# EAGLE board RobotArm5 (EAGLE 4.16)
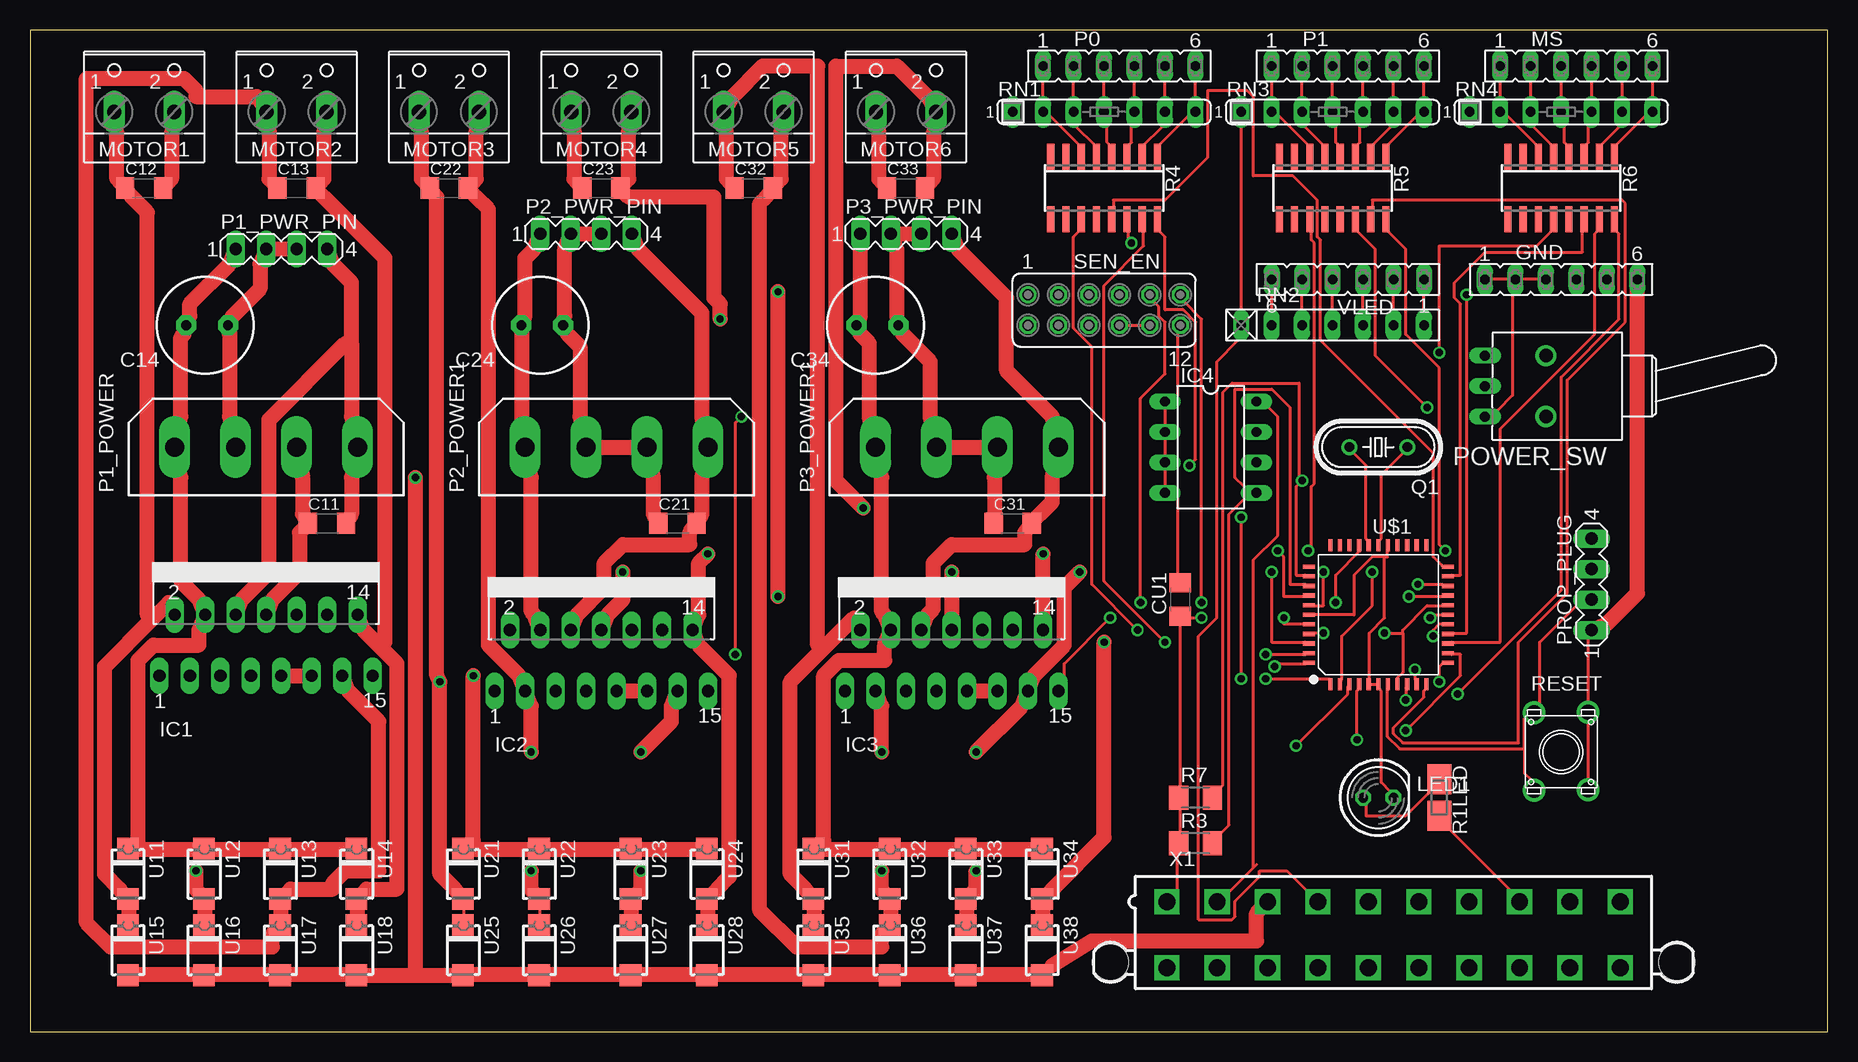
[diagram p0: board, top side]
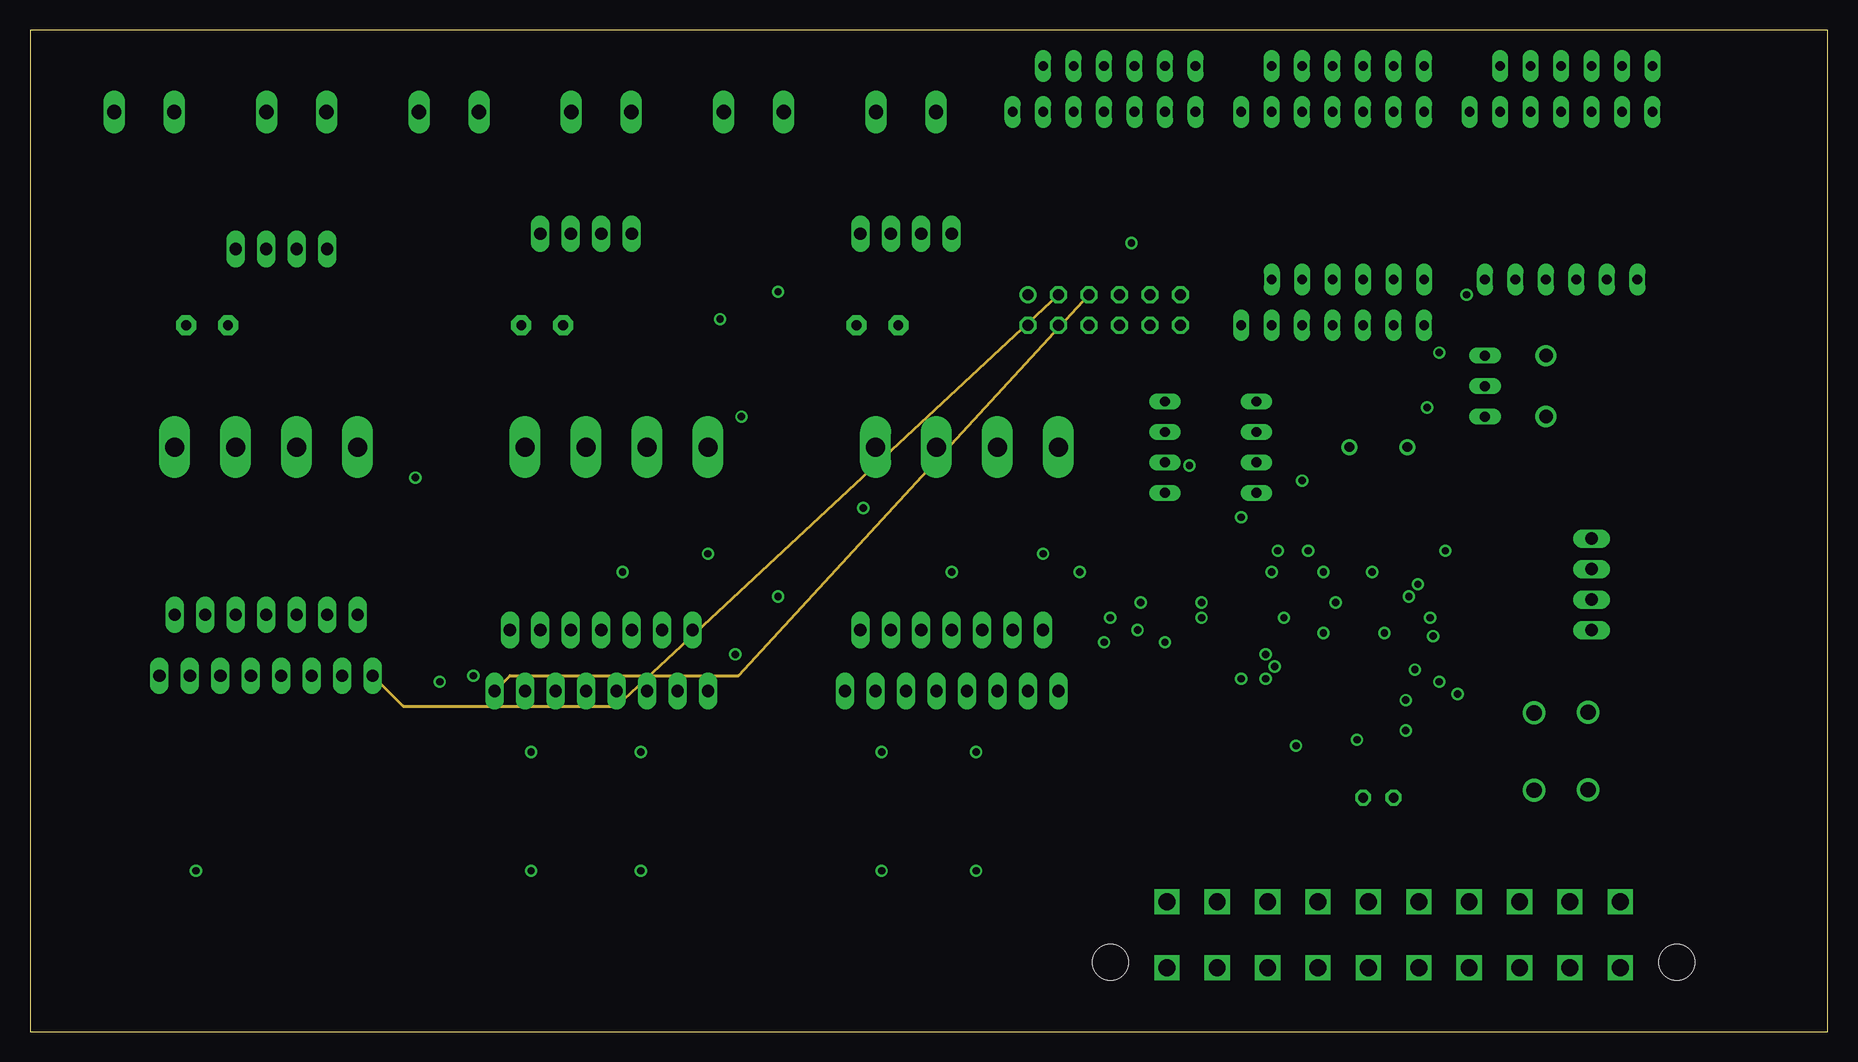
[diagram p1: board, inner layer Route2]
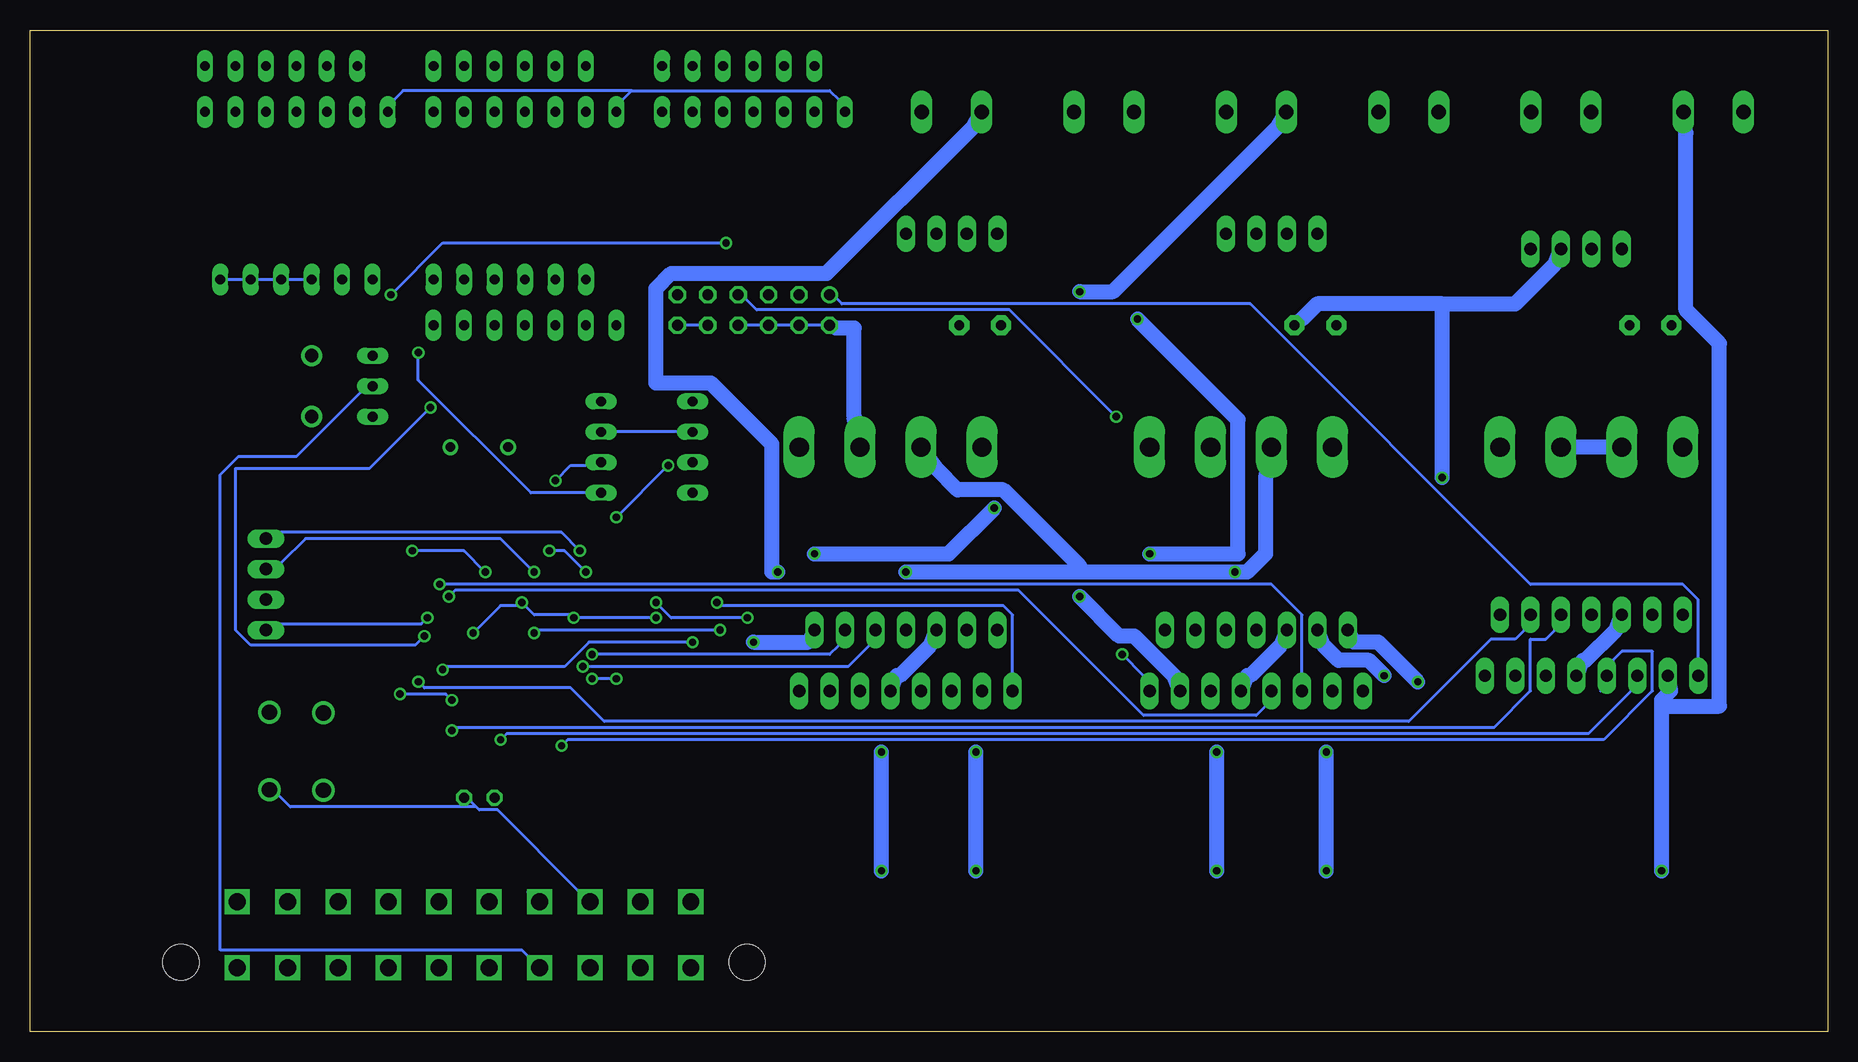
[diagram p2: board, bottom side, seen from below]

Size 149.84 x 83.49 mm. Coordinates in mm from the lower left corner, seen from the top.
Outline: 0,0 149.84,0 149.84,83.49 0,83.49 0,0
Copper layers (1*16): Top 0.035mm / dielectric 1.5mm / Bottom 0.035mm
Design rules "default": minimum track width 50mil, minimum drill 24mil, track to track 8mil, track to pad 8mil, pad to pad 8mil, via to via 8mil, smd to smd 8mil, copper to edge 40mil, drill to drill 8mil, minimum pad ring 10mil, minimum via ring 8mil, stop-mask expansion 4mil, vias tented up to drill 0mil, thermal gap 10mil

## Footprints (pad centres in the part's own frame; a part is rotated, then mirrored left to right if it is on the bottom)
1206 = smd 1.524 x 1.778: P$1 -1.587,0; P$2 1.587,0
ENP-035-080 = drill 0.813 pad 1.676 octagon: 1 -1.905,0; 2 1.587,0
C1206 = smd 1.6 x 1.8: 1 -1.4,0; 2 1.4,0
FE06 = drill 0.813 long: 1 -6.35,0; 2 -3.81,0; 3 -1.27,0; 4 1.27,0; 5 3.81,0; 6 6.35,0
MULTIWATT-15 = drill 1.016 long: 1 -8.89,-7.62; 2 -7.62,-2.54; 3 -6.35,-7.62; 4 -5.08,-2.54; 5 -3.81,-7.62; 6 -2.54,-2.54; 7 -1.27,-7.62; 8 0,-2.54; 9 1.27,-7.62; 10 2.54,-2.54; 11 3.81,-7.62; 12 5.08,-2.54; 13 6.35,-7.62; 14 7.62,-2.54; 15 8.89,-7.62
DIL08 = drill 0.813 long: 1 -3.81,-3.81; 2 -1.27,-3.81; 3 1.27,-3.81; 4 3.81,-3.81; 5 3.81,3.81; 6 1.27,3.81; 7 -1.27,3.81; 8 -3.81,3.81
LED5MM = drill 0.813 octagon: A -1.27,0; K 1.27,0
W237-102 = drill 1.194 long: 1 -2.5,-1.27; 2 2.5,-1.27
9090-4V = drill 1.6 pad 2.6 long: 1 -7.62,0; 2 -2.54,0; 3 2.54,0; 4 7.62,0
MA04-1 = drill 1.016 long: 1 -3.81,0; 2 -1.27,0; 3 1.27,0; 4 3.81,0
9070-1W = drill 0.813 long: 1 5.08,-2.54; 2 5.08,0; 3 5.08,2.54 | drill 1.118 pad 1.778 round: B 0,-2.54; B1 0,2.54
HC49/S = drill 0.813 round: 1 -2.413,0; 2 2.413,0
SMK = smd 2.5 x 2: 1 1.524,0; 2 -1.524,0
M1206 = smd 1.6 x 2: 1 -1.4,0; 2 1.4,0
SO16 = smd 0.6 x 2.2: 1 -4.445,-2.6; 2 -3.175,-2.6; 3 -1.905,-2.6; 4 -0.635,-2.6; 5 0.635,-2.6; 6 1.905,-2.6; 7 3.175,-2.6; 8 4.445,-2.6; 9 4.445,2.6; 10 3.175,2.6; 11 1.905,2.6; 12 0.635,2.6; 13 -0.635,2.6; 14 -1.905,2.6; 15 -3.175,2.6; 16 -4.445,2.6
FSMCD = drill 1.27 round: P$1 -2.25,3.25; P$2 -2.25,-3.2; P$3 2.25,3.3; P$4 2.25,-3.15
SIL7 = drill 0.813 long: 1 -7.62,0; 2 -5.08,0; 3 -2.54,0; 4 0,0; 5 2.54,0; 6 5.08,0; 7 7.62,0
RN-7 = drill 0.813 long: 1 -7.62,0; 2 -5.08,0; 3 -2.54,0; 4 0,0; 5 2.54,0; 6 5.08,0; 7 7.62,0
FE06-2 = drill 0.914 round: 1 -6.35,1.27 | drill 0.914 octagon: 2 -6.35,-1.27; 3 -3.81,1.27; 4 -3.81,-1.27; 5 -1.27,1.27; 6 -1.27,-1.27; 7 1.27,1.27; 8 1.27,-1.27; 9 3.81,1.27; 10 3.81,-1.27; 11 6.35,1.27; 12 6.35,-1.27
SMA = smd 1.8 x 1.8: 1 -2.1,-0.1; 2 2.1,-0.1
LQFP-44 = smd 0.35 x 1: 1 -4,-5.8; 2 -3.2,-5.8; 3 -2.4,-5.8; 4 -1.6,-5.8; 5 -0.8,-5.8; 6 0,-5.8; 7 0.8,-5.8; 8 1.6,-5.8; 9 2.4,-5.8; 10 3.2,-5.8; 11 4,-5.8; 23 4,5.8; 24 3.2,5.8; 25 2.4,5.8; 26 1.6,5.8; 27 0.8,5.8; 28 0,5.8; 29 -0.8,5.8; 30 -1.6,5.8; 31 -2.4,5.8; 32 -3.2,5.8; 33 -4,5.8 | smd 1 x 0.35: 12 5.8,-4; 13 5.8,-3.2; 14 5.8,-2.4; 15 5.8,-1.6; 16 5.8,-0.8; 17 5.8,0; 18 5.8,0.8; 19 5.8,1.6; 20 5.8,2.4; 21 5.8,3.2; 22 5.8,4; 34 -5.8,4; 35 -5.8,3.2; 36 -5.8,2.4; 37 -5.8,1.6; 38 -5.8,0.8; 39 -5.8,0; 40 -5.8,-0.8; 41 -5.8,-1.6; 42 -5.8,-2.4; 43 -5.8,-3.2; 44 -5.8,-4
5566-20 = drill 1.4 square: 1 18.9,-2.75; 2 14.7,-2.75; 3 10.5,-2.75; 4 6.3,-2.75; 5 2.1,-2.75; 6 -2.1,-2.75; 7 -6.3,-2.75; 8 -10.5,-2.75; 9 -14.7,-2.75; 10 -18.9,-2.75; 11 18.9,2.75; 12 14.7,2.75; 13 10.5,2.75; 14 6.3,2.75; 15 2.1,2.75; 16 -2.1,2.75; 17 -6.3,2.75; 18 -10.5,2.75; 19 -14.7,2.75; 20 -18.9,2.75 | hole 3: 23.6,2.29; -23.6,2.29

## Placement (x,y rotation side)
C11  .1uf  [1206]  24.76,42.38 0 top
C12  .1uf  [1206]  9.52,70.32 0 top
C13  .1uf  [1206]  22.22,70.32 0 top
C14  1000uf  [ENP-035-080]  14.6,58.89 180 top
C21  .1uf  [1206]  53.97,42.38 0 top
C22  .1uf  [1206]  34.92,70.32 0 top
C23  .1uf  [1206]  47.62,70.32 0 top
C24  1000uf  [ENP-035-080]  42.54,58.89 180 top
C31  .1uf  [1206]  81.91,42.38 0 top
C32  .1uf  [1206]  60.32,70.32 0 top
C33  .1uf  [1206]  73.02,70.32 0 top
C34  1000uf  [ENP-035-080]  70.48,58.89 180 top
CU1  1uf  [C1206]  95.88,36.03 90 top
GND  [FE06]  127.63,62.7 0 top
IC1  L298  [MULTIWATT-15]  19.68,37.3 0 top
IC2  L298  [MULTIWATT-15]  47.62,36.03 0 top
IC3  L298  [MULTIWATT-15]  76.83,36.03 0 top
IC4  AT24CP  [DIL08]  98.42,48.73 270 top
LED1  [LED5MM]  112.39,19.52 0 top
MOTOR1  [W237-102]  9.52,77.94 0 top
MOTOR2  [W237-102]  22.22,77.94 0 top
MOTOR3  [W237-102]  34.92,77.94 0 top
MOTOR4  [W237-102]  47.62,77.94 0 top
MOTOR5  [W237-102]  60.32,77.94 0 top
MOTOR6  [W237-102]  73.02,77.94 0 top
MS  [FE06]  128.9,80.48 0 top
P0  [FE06]  90.8,80.48 0 top
P1  [FE06]  109.85,80.48 0 top
P1_POWER  9090-4V  [9090-4V]  19.68,48.73 0 top
P1_PWR_PIN  [MA04-1]  20.95,65.24 0 top
P2_POWER1  9090-4V  [9090-4V]  48.89,48.73 0 top
P2_PWR_PIN  [MA04-1]  46.35,66.51 0 top
P3_POWER1  9090-4V  [9090-4V]  78.1,48.73 0 top
P3_PWR_PIN  [MA04-1]  73.02,66.51 0 top
POWER_SW  [9070-1W]  126.36,53.81 180 top
PROP_PLUG  [MA04-1]  130.17,37.3 90 top
Q1  [HC49/S]  112.39,48.73 180 top
R1LED  330ohm  [SMK]  117.47,19.52 270 top
R3  10K  [M1206]  97.15,15.71 0 top
R4  270ohm  [SO16]  89.53,70.32 180 top
R5  270ohm  [SO16]  108.58,70.32 180 top
R6  270ohm  [SO16]  127.63,70.32 180 top
R7  10K  [M1206]  97.15,19.52 0 top
RESET  FSMCD  [FSMCD]  127.63,23.33 0 top
RN1  10K  [SIL7]  89.53,76.67 0 top
RN2  [RN-7]  108.58,58.89 0 top
RN3  10K  [SIL7]  108.58,76.67 0 top
RN4  10K  [SIL7]  127.63,76.67 0 top
SEN_EN  [FE06-2]  89.53,60.16 0 top
U11  SSA34  [SMA]  8.25,13.17 270 top
U12  SSA34  [SMA]  14.6,13.17 270 top
U13  SSA34  [SMA]  20.95,13.17 270 top
U14  SSA34  [SMA]  27.3,13.17 270 top
U15  SSA34  [SMA]  8.25,6.82 270 top
U16  SSA34  [SMA]  14.6,6.82 270 top
U17  SSA34  [SMA]  20.95,6.82 270 top
U18  SSA34  [SMA]  27.3,6.82 270 top
U21  SSA34  [SMA]  36.19,13.17 270 top
U22  SSA34  [SMA]  42.54,13.17 270 top
U23  SSA34  [SMA]  50.16,13.17 270 top
U24  SSA34  [SMA]  56.51,13.17 270 top
U25  SSA34  [SMA]  36.19,6.82 270 top
U26  SSA34  [SMA]  42.54,6.82 270 top
U27  SSA34  [SMA]  50.16,6.82 270 top
U28  SSA34  [SMA]  56.51,6.82 270 top
U31  SSA34  [SMA]  65.4,13.17 270 top
U32  SSA34  [SMA]  71.75,13.17 270 top
U33  SSA34  [SMA]  78.1,13.17 270 top
U34  SSA34  [SMA]  84.45,13.17 270 top
U35  SSA34  [SMA]  65.4,6.82 270 top
U36  SSA34  [SMA]  71.75,6.82 270 top
U37  SSA34  [SMA]  78.1,6.82 270 top
U38  SSA34  [SMA]  84.45,6.82 270 top
U$1  P8X32A  [LQFP-44]  112.39,34.76 0 top
VLED  [FE06]  109.85,62.7 180 top
X1  5566-20  [5566-20]  113.66,8.09 180 top

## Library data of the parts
C11-C14 C21-C24 C31-C34 = zz-cap-master
CU1 = zz-rcl
GND MS P0 P1 SEN_EN VLED = con-lsta
IC1-IC3 = zz-st-microelectronics
IC4 = atmel
LED1 = led
MOTOR1-MOTOR6 = con-wago-500
P1_POWER P2_POWER1 P3_POWER1 = con-thomas-betts
P1_PWR_PIN P2_PWR_PIN P3_PWR_PIN PROP_PLUG = con-lstb
POWER_SW = switch
Q1 = crystal
R1LED = resistor-shunt
R3 R7 = rcl
R4-R6 = resistor-bourns
RESET = zz-switch-misc
RN1 RN3 RN4 = resistor-sil
RN2 = resistor-net
U11-U18 U21-U28 U31-U38 = diode-20CJQ030
U$1 = propeller
X1 = con-molex

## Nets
3.3VCC1: CU1.1 R3.1 R7.1 U$1.8 U$1.18 U$1.30 U$1.40 X1.1
5VCC: RN1.1 RN2.1 RN3.1 RN4.1 X1.4
CTL1: IC1.7 U$1.3
CTL2: IC1.12 U$1.12
CTL3: IC2.7 U$1.19
CTL4: IC2.12
CTL5: IC3.7
CTL6: IC3.12 U$1.43
GND: C11.P$1 C14.1 C21.P$1 C24.1 C31.P$1 C34.1 CU1.2 GND.1 GND.2 GND.3 GND.4 GND.5 GND.6 IC1.8 IC2.8 IC3.8 IC4.1 IC4.2 IC4.3 IC4.4 IC4.7 LED1.K P1_POWER.2 P1_POWER.3 P1_PWR_PIN.2 P1_PWR_PIN.3 P2_POWER1.2 P2_POWER1.3 P2_PWR_PIN.2 P2_PWR_PIN.3 P3_POWER1.2 P3_POWER1.3 P3_PWR_PIN.2 P3_PWR_PIN.3 POWER_SW.3 PROP_PLUG.1 RESET.P$3 RESET.P$4 SEN_EN.2 SEN_EN.4 SEN_EN.6 SEN_EN.8 SEN_EN.10 SEN_EN.12 U15.2 U16.2 U17.2 U18.2 U25.2 U26.2 U27.2 U28.2 U35.2 U36.2 U37.2 U38.2 U$1.5 U$1.6 U$1.17 U$1.27 U$1.39 X1.3
M5GND: C13.P$2 IC1.14 MOTOR2.2 U14.2 U18.1
M5GND1: C23.P$2 IC2.14 MOTOR4.2 U24.2 U28.1
M5GND2: C33.P$2 IC3.14 MOTOR6.2 U34.2 U38.1
M5VCC: C13.P$1 IC1.13 MOTOR2.1 U13.2 U17.1
M5VCC1: C23.P$1 IC2.13 MOTOR4.1 U23.2 U27.1
M5VCC2: C33.P$1 IC3.13 MOTOR6.1 U33.2 U37.1
M6GND: C12.P$2 IC1.3 MOTOR1.2 U12.2 U16.1
M6GND1: C22.P$2 IC2.3 MOTOR3.2 U22.2 U26.1
M6GND2: C32.P$2 IC3.3 MOTOR5.2 U32.2 U36.1
M6VCC: C12.P$1 IC1.2 MOTOR1.1 U11.2 U15.1
M6VCC1: C22.P$1 IC2.2 MOTOR3.1 U21.2 U25.1
M6VCC2: C32.P$1 IC3.2 MOTOR5.1 U31.2 U35.1
N$1: RN2.2 VLED.6
N$2: RN2.3 VLED.5
N$3: POWER_SW.2 X1.14
N$4: R1LED.1 X1.8
N$5: RN2.4 VLED.4
N$6: LED1.A R1LED.2
N$7: P1.1 R5.6 RN3.2
N$8: RN2.5 VLED.3
N$9: RN2.6 VLED.2
N$10: RN2.7 VLED.1
N$11: P1.2 R5.5 RN3.3
N$12: P0.3 R4.4 RN1.4
N$13: Q1.2 U$1.29
N$14: Q1.1 U$1.28
N$15: P0.4 R4.3 RN1.5
N$16: P0.5 R4.2 RN1.6
N$17: P0.6 R4.1 RN1.7
N$18: P1.3 R5.4 RN3.4
N$19: P1.4 R5.3 RN3.5
N$20: P1.5 R5.2 RN3.6
N$21: P1.6 R5.1 RN3.7
N$22: MS.6 R6.1 RN4.7
N$23: MS.5 R6.2 RN4.6
N$24: MS.4 R6.3 RN4.5
N$25: MS.3 R6.4 RN4.4
N$26: MS.2 R6.5 RN4.3
N$27: MS.1 R6.6 RN4.2
NC1: R6.11
P0: R4.11 U$1.41
P0_1: P0.1 R4.6 RN1.2
P0_2: P0.2 R4.5 RN1.3
P1: R5.11 U$1.42
P1_5V: C11.P$2 IC1.6 IC1.9 IC1.11 P1_POWER.4 P1_PWR_PIN.4
P1_12V: C14.2 IC1.4 P1_POWER.1 P1_PWR_PIN.1 U11.1 U12.1 U13.1 U14.1
P2_5V: C21.P$2 IC2.6 IC2.9 IC2.11 P2_POWER1.4 P2_PWR_PIN.4
P2_12V: C24.2 IC2.4 P2_POWER1.1 P2_PWR_PIN.1 U21.1 U22.1 U23.1 U24.1
P3_5V: C31.P$2 IC3.6 IC3.9 IC3.11 P3_POWER1.4 P3_PWR_PIN.4
P3_12V: C34.2 IC3.4 P3_POWER1.1 P3_PWR_PIN.1 U31.1 U32.1 U33.1 U34.1
P4: R4.16 U$1.1
P5: R5.16 U$1.2
P8: R6.16 U$1.9
P9: R4.15 U$1.10
P10: R5.15 U$1.11
P13: R6.15 U$1.14
P14: R4.14 U$1.15
P15: R5.14 U$1.16
P18: R6.14 U$1.21
P19: R4.13 U$1.22
P20: R5.13
P23: R6.13
P24: R4.12
P25: R5.12
P28: IC4.6 R7.2 U$1.35
P29: IC4.5 R3.2 R6.12 U$1.36
P30: PROP_PLUG.4 U$1.37
P31: PROP_PLUG.3 U$1.38
PWM1: IC1.5 U$1.4
PWM2: IC1.10 U$1.13
PWM3: IC2.5 U$1.20
PWM4: IC2.10
PWM5: IC3.5
PWM6: IC3.10 U$1.44
RES: PROP_PLUG.2 RESET.P$1 RESET.P$2 U$1.7
SEN_1: IC1.1 SEN_EN.1
SEN_2: IC1.15 SEN_EN.3
SEN_3: IC2.1 SEN_EN.5
SEN_4: IC2.15 SEN_EN.7
SEN_5: IC3.1 SEN_EN.9
SEN_6: IC3.15 SEN_EN.11
VCC3.3V2: IC4.8 X1.2

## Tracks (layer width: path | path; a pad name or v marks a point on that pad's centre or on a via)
3.3VCC1  (via drill 0.61)
  Top 0.254: X1.1 95.63,11.65 95.63,14.95 R3.1 95.88,16.47 95.88,18.76 R7.1 95.88,20.28 CU1.1 96.64,34.51 v97.66,34.51 | 114.42,33.24 114.42,33.49 116.45,35.52 117.72,35.52 U$1.18 | 114.42,33.24 114.42,29.93 113.91,29.43 U$1.8 | v104.52,34.51 104.52,34 106.29,34 U$1.40 | v108.83,35.78 108.83,38.06 110.87,40.09 U$1.30 | v112.9,33.24 114.42,33.24
  Bottom 0.254: v97.66,34.51 v104.52,34.51 104.77,34.76 107.82,34.76 v108.83,35.78 109.09,35.52 110.61,35.52 v112.9,33.24
5VCC
  Top 0.254: RN3.1 RN2.1 100.71,57.62 98.93,55.84 98.93,34.51 97.4,32.98 97.4,9.36 100.2,9.36 100.45,9.61 100.45,10.88 102.48,12.92 102.48,13.42 104.77,13.42 106.55,11.65 X1.4
  Bottom 0.254: 99.69,78.45 83.18,78.45 82.42,77.69 RN1.1 | 99.69,78.45 100.45,77.69 RN3.1 | 99.69,78.45 118.74,78.45 119.5,77.69 RN4.1 | X1.4 108.33,11.65
CTL1  (via drill 0.61)
  Top 0.254: v105.53,23.84 109.85,28.16 109.85,28.66 U$1.3
  Bottom 0.254: 18.92,28.41 IC1.7 17.9,30.95 17.14,31.71 14.6,31.71 14.6,28.41 18.66,24.35 105.02,24.35 v105.53,23.84
CTL2  (via drill 0.61)
  Top 0.254: v117.47,29.17 117.47,30.44 117.72,30.7 U$1.12
  Bottom 0.254: v117.47,29.17 116.96,28.66 104.77,28.66 101.98,25.87 34.92,25.87 28.06,32.73 26.03,32.73 25.27,33.49 IC1.12
CTL3  (via drill 0.61)
  Top 0.254: v114.93,36.28 117.72,36.28 U$1.19
  Bottom 0.254: v114.93,36.28 114.42,36.79 67.43,36.79 57.02,26.38 47.62,26.38 46.86,27.14 IC2.7
CTL6  (via drill 0.61)
  Top 0.254: v102.99,31.46 106.29,31.46 U$1.43
  Bottom 0.254: v102.99,31.46 83.18,31.46 82.42,32.22 IC3.12
GND  (via drill 0.61)
  Top 0.254: U35.2 66.16,4.79 | 70.99,4.79 U36.2 72.51,4.79 | 78.86,4.79 U37.2 77.34,4.79 | 83.69,4.79 U38.2 85.21,5.55 | U25.2 36.95,4.79 | 41.78,4.79 U26.2 43.3,4.79 | 50.92,4.79 U27.2 49.4,4.79 | 55.75,4.79 U28.2 | X1.3 104.01,11.65 | U15.2 9.01,4.79 | 13.84,4.79 U16.2 15.36,4.79 | 21.71,4.79 U17.2 20.19,4.79 | 26.54,4.79 U18.2 26.54,5.55 | GND.2 GND.1 | GND.3 GND.2 | CU1.2 95.63,38.06 95.63,44.41 IC4.4 IC4.3 IC4.2 IC4.1 95.63,53.05 95.63,58.38 SEN_EN.12 | SEN_EN.8 SEN_EN.10 | RESET.P$4 129.92,21.04 129.92,25.87 RESET.P$3 129.92,27.39 129.92,32.98 PROP_PLUG.1 | v116.71,34.51 116.71,34.76 U$1.17 | POWER_SW.3 122.3,51.78 123.57,53.05 123.57,61.43 GND.2 | 112.9,39.59 113.15,39.59 113.15,40.09 U$1.27 | 112.9,39.59 111.88,39.59 110.36,38.06 110.36,34.76 U$1.39 | LED1.K 113.41,20.03 112.64,20.79 112.64,28.41 112.39,28.66 U$1.6 112.39,28.92 111.63,28.92 U$1.5 111.63,29.43 111.63,33.24 112.9,34.51 112.9,39.59
  Top 0.406: U25.2 36.19,4.72 36.19,4.28
  Top 1.27: 66.16,4.79 70.99,4.79 | 78.86,4.79 83.69,4.79 | 72.51,4.79 77.34,4.79 | 36.95,4.79 41.78,4.79 | 50.92,4.79 55.75,4.79 | 43.3,4.79 49.4,4.79 | 85.21,5.55 88.51,7.58 102.23,7.58 102.23,9.87 X1.3 | 9.01,4.79 13.84,4.79 | 21.71,4.79 26.54,4.79 | 15.36,4.79 20.19,4.79 | U18.2 32.13,4.72 | 32.13,4.72 36.19,4.72 | P1_PWR_PIN.3 P1_PWR_PIN.2 19.17,63.97 19.17,61.94 16.89,59.65 C14.1 16.63,58.13 16.63,51.27 P1_POWER.2 | P1_POWER.3 22.73,46.19 22.73,43.14 C11.P$1 22.47,41.62 22.47,38.32 20.19,36.03 IC1.8 | P3_PWR_PIN.3 P3_PWR_PIN.2 72.26,65.24 72.26,59.65 C34.1 72.77,58.13 75.05,55.84 75.05,51.27 P3_POWER1.2 P3_POWER1.3 80.39,46.19 80.39,43.14 C31.P$1 | P2_PWR_PIN.3 P2_PWR_PIN.2 44.57,65.24 44.57,59.65 C24.1 44.83,58.13 45.84,57.11 45.84,51.27 P2_POWER1.2 P2_POWER1.3 51.94,46.19 51.94,43.14 C21.P$1 | v49.4,38.32 49.4,36.03 48.13,34.76 IC2.8 | v76.83,38.32 IC3.8 | GND.6 133.98,36.54 131.44,34 PROP_PLUG.1 | U35.2 64.64,4.79 57.27,4.79 U28.2 | 32.13,4.72 v32.13,46.19
  Bottom 0.254: GND.6 GND.5 GND.4 GND.3 | IC4.2 IC4.7 | SEN_EN.10 SEN_EN.12 | SEN_EN.8 SEN_EN.6 SEN_EN.4 SEN_EN.2 | v116.71,34.51 117.22,34 128.9,34 PROP_PLUG.1 | 112.64,18.76 113.15,19.27 LED1.K | 112.64,18.76 112.39,18.5 110.87,18.5 104.01,11.65 X1.3 | 112.64,18.76 128.14,18.76 129.15,19.77 RESET.P$4
  Bottom 1.27: P1_POWER.2 P1_POWER.3 | P3_POWER1.3 81.15,51.27 81.15,58.64 82.67,58.64 SEN_EN.2 | P2_POWER1.2 46.86,46.19 46.86,39.84 48.38,38.32 v49.4,38.32 62.35,38.32 | 62.35,38.32 v76.83,38.32 | P3_POWER1.2 74.29,46.95 72.51,45.17 68.7,45.17 62.35,38.82 62.35,38.32 | 32.13,60.67 42.54,60.67 43.81,59.4 C24.1 | 32.13,60.67 26.03,60.67 22.73,63.97 P1_PWR_PIN.3 | v32.13,46.19 32.13,60.67
M5GND
  Top 0.254: U18.1 27.3,9.61 | 27.3,10.38 U14.2
  Top 1.27: 27.3,9.61 27.3,10.38 | MOTOR2.2 24.51,74.89 24.51,71.08 C13.P$2 24.51,69.56 29.59,64.48 29.59,32.47 29.2,32.09 | 29.2,32.09 27.81,33.49 IC1.14 | 29.2,32.09 30.6,30.7 30.6,11.9 28.06,11.9 U14.2
M5GND1  (via drill 0.61)
  Top 0.254: U28.1 56.51,9.61 | 56.51,10.38 U24.2
  Top 1.27: 56.51,9.61 56.51,10.38 | MOTOR4.2 49.91,74.89 49.91,71.08 C23.P$2 49.91,69.56 57.02,69.56 57.02,61.18 57.53,60.67 v57.53,59.4 | U24.2 57.27,11.9 58.29,12.92 58.29,29.68 55.75,32.22 IC2.14 55.75,34.76 55.75,39.08 v56.51,39.84
  Bottom 1.27: v57.53,59.4 49.14,51.02 49.14,39.84 v56.51,39.84
M5GND2  (via drill 0.61)
  Top 0.254: U38.1 84.45,9.61 | 84.45,10.38 U34.2
  Top 1.27: 84.45,9.61 84.45,10.38 | C33.P$2 75.31,71.08 75.31,74.89 MOTOR6.2 74.8,77.94 72.26,80.48 67.18,80.48 67.18,45.94 v69.46,43.65 | v89.53,32.47 89.53,16.22 85.21,11.9 U34.2 | IC3.14 v84.45,39.84
  Bottom 1.27: v89.53,32.47 84.96,32.47 IC3.14 | v69.46,43.65 73.27,39.84 v84.45,39.84
M5VCC
  Top 0.254: U17.1 20.95,9.61 | 20.95,10.38 U13.2
  Top 1.27: 20.95,9.61 20.95,10.38 | C13.P$1 19.93,71.08 19.93,74.89 MOTOR2.1 18.92,77.94 13.84,77.94 13.84,78.45 12.82,79.46 4.69,79.46 4.69,9.11 6.73,7.07 20.19,7.07 20.19,8.09 U17.1 | U13.2 21.71,11.9 25.27,11.9 25.27,12.41 26.28,13.42 29.08,13.42 29.08,25.87 26.54,28.41 IC1.13
M5VCC1  (via drill 0.61)
  Top 0.254: U27.1 50.16,9.61 | 50.16,10.38 U23.2
  Top 1.27: 50.16,9.61 50.16,10.38 | C23.P$1 45.33,71.08 45.33,74.89 MOTOR4.1 | v50.92,13.42 50.92,11.9 U23.2 | v50.92,23.33 53.46,25.87 53.46,27.14 IC2.13 | v62.35,36.28 v62.35,61.68
  Bottom 1.27: v50.92,13.42 v50.92,23.33 | v62.35,61.68 59.56,61.68 45.84,75.4 MOTOR4.1 | v62.35,36.28 59.05,32.98 57.78,32.98 54.48,29.68 IC2.13
M5VCC2  (via drill 0.61)
  Top 0.254: U37.1 78.1,9.61 | 78.1,10.38 U33.2
  Top 1.27: 78.1,9.61 78.1,10.38 | C33.P$1 70.73,71.08 70.73,74.89 MOTOR6.1 | v78.86,13.42 78.86,11.9 U33.2 | v78.86,23.33 82.67,27.14 IC3.13 83.69,29.68 86.23,32.22 86.23,37.05 v87.5,38.32
  Bottom 1.27: v78.86,13.42 v78.86,23.33 | v87.5,38.32 88.01,38.32 88.01,48.98 93.09,54.06 97.66,54.06 97.66,61.94 96.39,63.21 83.43,63.21 71.24,75.4 MOTOR6.1
M6GND  (via drill 0.61)
  Top 0.254: U16.1 14.6,9.61 | 14.6,10.38 U12.2
  Top 1.27: 14.6,9.61 14.6,10.38 | C12.P$2 11.81,71.08 11.81,74.89 MOTOR1.2 | v13.84,13.42 13.84,11.9 U12.2
  Bottom 1.27: 13.84,27.14 13.84,27.65 13.08,28.41 IC1.3 | v13.84,13.42 13.84,27.14 | MOTOR1.2 11.81,74.89 11.81,60.16 9.01,57.37 9.01,27.14 13.84,27.14
M6GND1  (via drill 0.61)
  Top 0.254: U26.1 42.54,9.61 42.54,10.38 U22.2
  Top 1.27: MOTOR3.2 37.21,74.89 37.21,71.08 C22.P$2 37.21,69.56 38.22,68.54 38.22,32.22 40.76,29.68 IC2.3 41.78,27.14 v41.78,23.33 | v41.78,13.42 41.78,11.9 U22.2
  Bottom 1.27: v41.78,13.42 v41.78,23.33
M6GND2  (via drill 0.61)
  Top 0.254: U36.1 71.75,9.61 | 71.75,10.38 U32.2
  Top 1.27: 71.75,9.61 71.75,10.38 | MOTOR5.2 62.61,74.89 62.61,71.08 C32.P$2 61.34,69.56 60.83,69.05 60.83,10.12 63.88,7.07 70.99,7.07 70.99,8.09 U36.1 | v70.99,13.42 70.99,11.9 U32.2 | v70.99,23.33 70.99,27.14 IC3.3
  Bottom 1.27: v70.99,13.42 v70.99,23.33
M6VCC
  Top 0.254: U15.1 8.25,9.61 | 8.25,10.38 U11.2
  Top 1.27: 8.25,9.61 8.25,10.38 | MOTOR1.1 7.23,74.89 7.23,71.08 C12.P$1 8.5,69.56 9.77,68.29 9.77,34.76 10.16,34.38 | 10.16,34.38 11.55,35.78 IC1.2 | 10.16,34.38 6.22,30.44 6.22,13.17 7.49,11.9 U11.2
M6VCC1  (via drill 0.61)
  Top 0.254: U25.1 36.19,9.61 36.19,10.38 U21.2
  Top 1.27: MOTOR3.1 32.63,74.89 32.63,71.08 C22.P$1 33.9,69.56 33.9,29.68 v34.16,29.17 34.16,13.17 35.43,11.9 U21.2
  Bottom 1.27: v34.16,29.17 37.46,32.47 39.49,32.47 IC2.2
M6VCC2
  Top 0.254: U35.1 65.4,9.61 | 65.4,10.38 U31.2
  Top 1.27: 65.4,9.61 65.4,10.38 | C32.P$1 58.03,71.08 58.03,74.89 MOTOR5.1 58.54,77.94 61.08,80.48 65.65,80.48 65.65,32.22 66.03,31.84 | 66.03,31.84 68.7,34.51 IC3.2 | 66.03,31.84 63.37,29.17 63.37,13.17 64.64,11.9 U31.2
N$1
  Top 0.254: RN2.2 VLED.6
N$2
  Top 0.254: RN2.3 VLED.5
N$3
  Bottom 0.254: POWER_SW.2 122.3,53.3 127.63,47.97 132.46,47.97 133.98,46.44 133.98,6.82 108.83,6.82 108.33,6.31 X1.14
N$4
  Top 0.254: R1LED.1 118.23,16.98 123.31,11.9 123.31,11.65 X1.8
N$5
  Top 0.254: RN2.4 VLED.4
N$6
  Top 0.254: R1LED.2 116.71,20.03 114.68,18 111.37,18 111.37,19.01 LED1.A
N$7
  Top 0.254: R5.6 106.55,73.88 104.01,76.42 RN3.2 P1.1
N$8
  Top 0.254: RN2.5 VLED.3
N$9
  Top 0.254: RN2.6 VLED.2
N$10
  Top 0.254: RN2.7 VLED.1
N$11
  Top 0.254: R5.5 107.82,73.88 106.29,75.4 RN3.3 P1.2
N$12
  Top 0.254: R4.4 90.04,73.88 89.78,74.13 89.78,75.4 RN1.4 P0.3
N$13
  Top 0.254: U$1.29 111.63,40.86 111.37,41.11 111.37,47.21 110.36,48.22 Q1.2
N$14
  Top 0.254: U$1.28 112.39,40.86 112.64,41.11 112.64,46.44 114.42,48.22 Q1.1
N$15
  Top 0.254: R4.3 91.56,73.88 91.82,74.13 91.82,75.4 RN1.5 P0.4
N$16
  Top 0.254: R4.2 92.83,73.88 94.36,75.4 RN1.6 P0.5
N$17
  Top 0.254: R4.1 94.1,73.88 96.64,76.42 RN1.7 P0.6
N$18
  Top 0.254: R5.4 109.09,73.88 108.83,74.13 108.83,75.4 RN3.4 P1.3
N$19
  Top 0.254: R5.3 110.61,73.88 110.87,74.13 110.87,75.4 RN3.5 P1.4
N$20
  Top 0.254: R5.2 111.88,73.88 113.41,75.4 RN3.6 P1.5
N$21
  Top 0.254: R5.1 113.15,73.88 115.69,76.42 RN3.7 P1.6
N$22
  Top 0.254: R6.1 132.2,73.88 134.74,76.42 RN4.7 MS.6
N$23
  Top 0.254: R6.2 130.93,73.88 132.46,75.4 RN4.6 MS.5
N$24
  Top 0.254: R6.3 129.66,73.88 129.92,74.13 129.92,75.4 RN4.5 MS.4
N$25
  Top 0.254: R6.4 128.14,73.88 127.88,74.13 127.88,75.4 RN4.4 MS.3
N$26
  Top 0.254: R6.5 126.87,73.88 125.34,75.4 RN4.3 MS.2
N$27
  Top 0.254: R6.6 125.6,73.88 123.06,76.42 RN4.2 MS.1
P0  (via drill 0.61)
  Top 0.254: R4.11 87.5,66.76 86.99,66.26 86.99,58.64 88.51,57.11 88.51,37.3 v92.32,33.49 | v107.82,33.24 107.06,33.24 U$1.41
  Bottom 0.254: v107.82,33.24 107.56,33.49 v92.32,33.49
P0_1
  Top 0.254: R4.6 87.5,73.88 84.96,76.42 RN1.2 P0.1
P0_2
  Top 0.254: R4.5 88.77,73.88 87.24,75.4 RN1.3 P0.2
P1  (via drill 0.61)
  Top 0.254: 106.55,66.76 R5.11 106.8,66.76 106.8,66 107.06,65.75 107.06,45.68 106.8,45.43 106.8,40.35 v106.55,40.09 | v103.5,38.32 103.5,32.47 106.29,32.47 U$1.42
  Bottom 0.254: v103.5,38.32 105.28,40.09 v106.55,40.09
P1_5V
  Top 0.254: C11.P$2 25.78,41.62
  Top 1.27: IC1.9 IC1.11 | C11.P$2 26.79,43.14 26.79,46.19 P1_POWER.4 26.79,51.27 26.79,57.37 | 26.79,57.37 26.79,62.45 25.27,63.97 P1_PWR_PIN.4 | IC1.6 17.65,36.03 19.93,38.32 19.93,51.02 26.28,57.37 26.79,57.37
  Bottom 1.27: IC1.6 17.65,33.49 20.19,30.95 20.44,30.95 IC1.9
P1_12V
  Top 0.254: U11.1 9.01,15.2 | 13.84,15.2 U12.1 15.36,15.2 | 21.71,15.2 U13.1 20.19,15.2 | 26.54,15.2 U14.1
  Top 1.27: 9.01,15.2 13.84,15.2 | 21.71,15.2 26.54,15.2 | 15.36,15.2 20.19,15.2 | P1_PWR_PIN.1 16.63,63.97 13.33,60.67 13.33,59.65 C14.2 12.82,58.13 12.57,57.87 12.57,51.27 P1_POWER.1 12.57,46.19 12.57,37.55 14.09,36.03 IC1.4 14.09,33.49 14.09,32.22 10.28,32.22 9.01,30.95 9.01,15.96 U11.1
P2_5V
  Top 1.27: IC2.9 IC2.11 | P2_PWR_PIN.4 50.67,65.24 56,59.91 56,51.27 P2_POWER1.4 56,46.19 56,43.14 C21.P$2 54.99,41.62 54.99,40.6 49.4,40.6 47.87,39.08 47.87,37.05 45.59,34.76 IC2.6
  Bottom 1.27: IC2.6 45.59,32.22 48.13,29.68 48.38,29.68 IC2.9
P2_12V  (via drill 0.61)
  Top 0.254: U21.1 36.95,15.2 | 41.78,15.2 U22.1 | 50.92,15.2 U23.1 49.4,15.2 | 55.75,15.2 U24.1 | U22.1 43.3,15.2 | U22.1 42.54,15.96
  Top 1.27: 36.95,15.2 41.78,15.2 | 50.92,15.2 55.75,15.2 | 43.3,15.2 49.4,15.2 | P2_PWR_PIN.1 42.03,65.24 41.27,64.48 41.27,59.65 C24.2 41.02,58.13 41.02,51.27 P2_POWER1.1 41.78,46.19 41.78,35.01 42.03,34.76 IC2.4 | v36.95,29.68 36.95,15.96 U21.1
  Bottom 1.27: v36.95,29.68 38.22,30.95 40.76,30.95 42.03,32.22 IC2.4
P3_5V
  Top 1.27: IC3.9 IC3.11 | P3_PWR_PIN.4 77.34,65.24 81.4,61.18 81.4,55.08 85.21,51.27 P3_POWER1.4 85.21,46.19 85.21,44.16 84.2,43.14 C31.P$2 82.93,41.62 82.93,40.6 76.83,40.6 75.31,39.08 75.31,35.27 74.8,34.76 IC3.6
  Bottom 1.27: IC3.6 74.8,32.22 77.34,29.68 77.59,29.68 IC3.9
P3_12V
  Top 0.254: U31.1 66.16,15.2 | 70.99,15.2 U32.1 72.51,15.2 | 78.86,15.2 U33.1 77.34,15.2 | 83.69,15.2 U34.1
  Top 1.27: 66.16,15.2 70.99,15.2 | 78.86,15.2 83.69,15.2 | 72.51,15.2 77.34,15.2 | P3_PWR_PIN.1 69.21,59.65 C34.2 69.21,58.13 69.97,57.37 69.97,51.27 P3_POWER1.1 70.99,46.19 70.99,35.01 71.24,34.76 IC3.4 71.24,32.22 71.24,30.95 67.43,30.95 66.16,29.68 66.16,15.96 U31.1
P4  (via drill 0.61)
  Top 0.254: R4.16 94.1,66.76 94.61,66.26 94.61,60.16 96.13,60.16 97.15,59.14 97.15,47.71 v96.64,47.21 | v102.99,29.43 108.33,29.43 U$1.1 | v100.96,29.43 v100.96,42.89
  Bottom 0.254: v100.96,29.43 v102.99,29.43 | v100.96,42.89 v96.64,47.21
P5  (via drill 0.61)
  Top 0.254: R5.16 113.15,66.76 114.68,65.24 114.68,58.13 117.47,55.33 117.47,40.6 v117.98,40.09 | v111.88,38.32 111.88,35.52 109.34,32.98 109.34,29.43 U$1.2
  Bottom 0.254: v111.88,38.32 113.66,40.09 v117.98,40.09
P8  (via drill 0.61)
  Top 0.254: v114.68,27.65 114.68,28.66 U$1.9 | v118.99,28.16 127.63,36.79 127.63,54.57 132.46,59.4 132.46,66.51 132.2,66.76 R6.16
  Bottom 0.254: v114.68,27.65 115.18,28.16 v118.99,28.16
P9  (via drill 0.61)
  Top 0.254: R4.15 92.83,66.76 92.83,65.49 89.53,62.19 89.53,37.55 v94.61,32.47 | v115.44,30.19 115.44,29.43 U$1.10
  Bottom 0.254: v115.44,30.19 115.18,30.44 105.28,30.44 103.25,32.47 v94.61,32.47
P10
  Top 0.254: 111.88,66.76 R5.15 111.88,68.8 111.88,69.3 132.71,69.3 132.96,69.05 132.96,59.14 128.14,54.32 128.14,36.54 124.07,32.47 124.07,24.09 114.42,24.09 113.66,24.85 113.66,25.36 116.2,27.9 116.2,28.41 116.45,28.66 U$1.11
P13
  Top 0.254: U$1.14 118.49,32.47 122.55,32.47 122.55,50.25 130.42,58.13 130.42,66.51 130.68,66.76 R6.15
P14  (via drill 0.61)
  Top 0.254: v91.82,65.75 91.56,66 91.56,66.76 R4.14 | v119.76,61.43 119.76,33.24 118.49,33.24 U$1.15
  Bottom 0.254: v91.82,65.75 115.44,65.75 v119.76,61.43
P15  (via drill 0.61)
  Top 0.254: v116.96,32.98 116.96,33.49 117.47,34 117.72,34 U$1.16 | v116.45,52.03 112.14,56.35 112.14,65.24 110.61,66.76 R5.14
  Bottom 0.254: v116.96,32.98 117.72,32.22 131.44,32.22 132.71,33.49 132.71,46.95 121.53,46.95 v116.45,52.03
P18
  Top 0.254: U$1.21 118.49,38.06 119.25,38.06 119.25,60.67 118.74,61.18 118.74,62.45 121.28,64.99 129.41,64.99 129.41,66.76 R6.14
P19
  Top 0.254: R4.13 90.29,68.8 90.29,69.3 94.61,69.3 98.17,72.86 98.17,78.45 101.47,78.45 101.98,77.94 101.98,71.34 105.28,71.34 107.31,69.3 107.31,66.26 107.56,66 107.56,57.62 116.96,48.22 116.96,39.59 117.72,38.82 U$1.22
P28  (via drill 0.61)
  Top 0.254: U$1.35 106.29,38.06 105.53,38.06 105.53,45.43 v106.04,45.94 105.79,46.19 105.79,54.06 100.2,54.06 99.44,53.3 99.44,20.54 99.18,20.28 R7.2
  Bottom 0.254: v106.04,45.94 104.77,47.21 103.5,47.21 IC4.6
P29  (via drill 0.61)
  Top 0.254: R6.12 126.87,66.76 125.6,65.49 117.47,65.49 v117.47,56.6 | U$1.36 106.29,37.3 105.02,37.3 105.02,52.03 103.5,53.56 100.45,53.56 100.45,46.19 101.21,45.43 IC4.5 101.21,44.41 99.94,43.14 99.94,17.23 99.18,16.47 R3.2
  Bottom 0.254: v117.47,56.6 117.47,54.32 108.07,44.92 IC4.5
P30  (via drill 0.61)
  Top 0.254: v104.01,40.09 104.52,39.59 104.52,36.28 106.29,36.28 U$1.37
  Bottom 0.254: v104.01,40.09 105.53,41.62 128.9,41.62 PROP_PLUG.4
P31  (via drill 0.61)
  Top 0.254: v107.82,38.32 107.82,35.52 107.06,35.52 U$1.38
  Bottom 0.254: v107.82,38.32 110.61,41.11 126.87,41.11 128.9,39.08 PROP_PLUG.3
PWM1  (via drill 0.61)
  Top 0.254: v110.61,24.35 110.61,28.41 110.87,28.66 U$1.4
  Bottom 0.254: v110.61,24.35 110.1,24.85 19.93,24.85 16.38,28.41 IC1.5
PWM2  (via drill 0.61)
  Top 0.254: v114.68,25.11 119.25,29.68 119.25,31.46 118.49,31.46 U$1.13
  Bottom 0.254: v114.68,25.11 114.42,25.36 27.81,25.36 24.76,28.41 24.76,32.73 23.49,32.73 22.73,33.49 IC1.10
PWM3  (via drill 0.61)
  Top 0.254: v115.69,37.3 117.72,37.3 U$1.20
  Bottom 0.254: v115.69,37.3 46.35,37.3 43.81,34.76 IC2.5
PWM6  (via drill 0.61)
  Top 0.254: v103.75,30.44 103.75,30.7 106.29,30.7 U$1.44
  Bottom 0.254: v103.75,30.44 81.66,30.44 79.88,32.22 IC3.10
RES
  Top 0.254: 124.58,23.58 114.17,23.58 113.15,24.6 113.15,28.66 U$1.7 | 124.58,23.58 124.58,26.12 RESET.P$1 125.85,27.39 125.85,32.47 128.9,35.52 PROP_PLUG.2 | 124.58,23.58 124.58,21.55 125.09,21.04 RESET.P$2
SEN_1
  Bottom 0.254: IC1.1 10.79,36.03 12.06,37.3 24.76,37.3 48.13,60.67 82.16,60.67 82.67,61.18 SEN_EN.1
SEN_2
  Route2 0.254: SEN_EN.3 48.89,27.14 31.11,27.14 IC1.15
SEN_3
  Route2 0.254: SEN_EN.5 59.05,29.68 40,29.68 IC2.1
SEN_4  (via drill 0.61)
  Top 0.254: v59.3,51.27 58.8,50.76 v58.8,31.46
  Bottom 0.254: v59.3,51.27 68.19,60.16 89.28,60.16 90.29,61.18 SEN_EN.7 | v58.8,31.46 57.02,29.68 IC2.15
SEN_5  (via drill 0.61)
  Top 0.254: v92.58,35.78 92.58,52.79 94.61,54.83 94.61,59.14 94.1,59.65 94.1,60.41 93.59,60.92 SEN_EN.9
  Bottom 0.254: v92.58,35.78 92.32,35.52 68.7,35.52 67.94,34.76 IC3.1
SEN_6  (via drill 0.61)
  Top 0.254: v97.66,35.78 97.66,59.4 96.13,60.92 SEN_EN.11 | v90.04,34.51 86.23,30.7 86.23,29.68 IC3.15
  Bottom 0.254: v97.66,35.78 96.39,34.51 v90.04,34.51
VCC3.3V2
  Top 0.254: 101.98,13.68 99.94,11.65 X1.2 | 101.98,13.68 102.23,13.93 | 101.98,13.68 101.98,39.33 104.01,41.36 104.01,51.27 103.25,52.03 IC4.8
